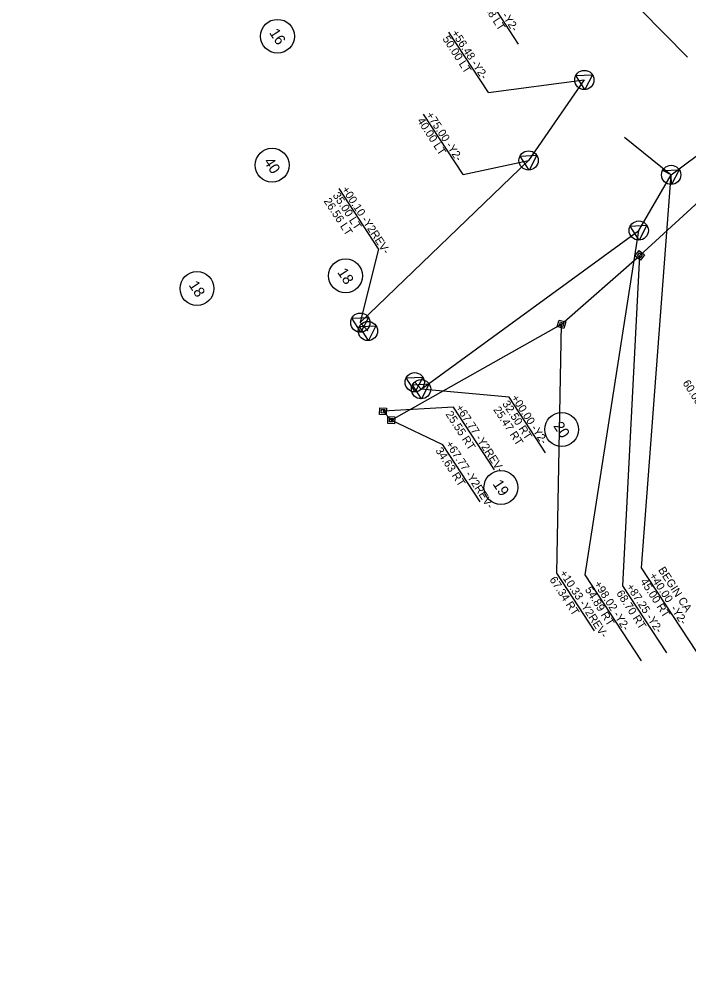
# Model space of a CAD drawing. Extents: x 1638966 to 1642158, y 841755 to 844938.
# Drawn here: x 1639805 to 1640306, y 843001 to 843723 of the extents above; entities that cross this region are included whole.
import ezdxf

# ---------------------------------------------------------------- set-up
doc = ezdxf.new("R2010")
doc.units = 0
for name, color, linetype in [('Exist Building', 7, 'Continuous'), ('Exist Guardrail Text', 7, 'Continuous'), ('Exist Other Culture Fence Line Text', 7, 'Continuous'), ('Exist Structure Major Deck Tunnel Box Culvert Text', 7, 'Continuous'), ('Exist Structure Minor Pipes CMP 18 Inch Text', 7, 'Continuous'), ('Exist Structure Minor Pipes CMP 24 Inch', 7, 'Continuous'), ('Exist Structure Minor Pipes RCP 24 Inch', 7, 'Continuous'), ('P_RDY_ROW_RW_CA_Lines', 7, 'Continuous'), ('Prop ROW Marker CA CELL', 7, 'Continuous'), ('Prop ROW Marker CELL', 7, 'Continuous')]:
    doc.layers.add(name, color=color, linetype=linetype)

msp = doc.modelspace()

# ---------------------------------------------------------------- linework, layer by layer
at = {"layer": 'Exist Building'}
for centre in [(1639998.43, 843710.36), (1639994.35, 843613.75), (1640049.39, 843530.85), (1639938.12, 843521.31), (1640211.14, 843415.72), (1640165.7, 843372.27)]:
    msp.add_circle(centre, 12.69, dxfattribs=at)
at = {"layer": 'Exist Guardrail Text'}
for p, q in [((1640156.32, 843668.13), (1640126.77, 843713.42)), ((1640137.31, 843606.79), (1640107.76, 843652.09)), ((1640271.05, 843312.1), (1640293.13, 843606.47)), ((1640074.1, 843550.98), (1640044.55, 843596.27)), ((1640228.83, 843306.86), (1640268.88, 843564.8)), ((1640171.81, 843439.81), (1640105.89, 843445.88)), ((1640199.01, 843398.12), (1640171.81, 843439.81)), ((1640312.04, 843249.28), (1640271.05, 843312.1)), ((1640270.86, 843242.45), (1640228.83, 843306.86))]:
    msp.add_line(p, q, dxfattribs=at)
for points in [[(1640156.32, 843668.13), (1640228.12, 843677.62)], [(1640137.31, 843606.79), (1640186.42, 843617.33)], [(1640074.1, 843550.98), (1640060.43, 843495.78)]]:
    msp.add_lwpolyline(points, dxfattribs=at)
at = {"layer": 'Exist Other Culture Fence Line Text'}
for points in [[(1640228.12, 843677.62), (1640186.42, 843617.33), (1640060.43, 843495.78), (1640066.12, 843489.53)], [(1640101.15, 843451.09), (1640105.89, 843445.88), (1640268.88, 843564.8), (1640293.13, 843606.47)], [(1640105.89, 843445.88), (1640101.15, 843451.09)]]:
    msp.add_lwpolyline(points, dxfattribs=at)
msp.add_arc((1640160.09, 843356.15), 355, 34.94361, 34.94361, dxfattribs=at)
at = {"layer": 'Exist Structure Major Deck Tunnel Box Culvert Text'}
msp.add_line((1640258.15, 843634.77), (1640293.13, 843606.47), dxfattribs=at)
msp.add_lwpolyline([(1640270.22, 843730.36), (1640305.26, 843694.61)], dxfattribs=at)
at = {"layer": 'Exist Structure Minor Pipes CMP 18 Inch Text'}
msp.add_line((1640178.92, 843704.51), (1640149.58, 843749.48), dxfattribs=at)
at = {"layer": 'Exist Structure Minor Pipes CMP 24 Inch'}
for p, q in [((1640257.02, 843298.67), (1640269.63, 843546.21)), ((1640207.51, 843308.13), (1640211.05, 843494.56)), ((1640130.11, 843432.48), (1640077.43, 843429.36)), ((1640160.76, 843385.52), (1640130.11, 843432.48)), ((1640122.25, 843404.14), (1640083.58, 843422.67)), ((1640150.11, 843361.45), (1640122.25, 843404.14)), ((1640235.8, 843264.77), (1640207.51, 843308.13)), ((1640289.91, 843248.26), (1640257.02, 843298.67))]:
    msp.add_line(p, q, dxfattribs=at)
at = {"layer": 'Exist Structure Minor Pipes RCP 24 Inch'}
for p, q in [((1640269.63, 843546.21), (1640348.28, 843618.3)), ((1640269.63, 843546.21), (1640269.63, 843546.21)), ((1640211.05, 843494.56), (1640211.05, 843494.56)), ((1640077.43, 843429.36), (1640077.43, 843429.36)), ((1640083.58, 843422.67), (1640083.58, 843422.67))]:
    msp.add_line(p, q, dxfattribs=at)
for points in [[(1640269.15, 843549.78), (1640273.2, 843546.69), (1640270.11, 843542.64), (1640266.06, 843545.73)], [(1640269.39, 843547.99), (1640271.42, 843546.45), (1640269.87, 843544.43), (1640267.85, 843545.97)], [(1640209.29, 843497.69), (1640214.19, 843496.32), (1640212.82, 843491.42), (1640207.92, 843492.79)], [(1640210.17, 843496.12), (1640212.62, 843495.44), (1640211.94, 843492.99), (1640209.49, 843493.67)], [(1640075, 843432.01), (1640080.08, 843431.79), (1640079.87, 843426.71), (1640074.78, 843426.92)], [(1640076.21, 843430.68), (1640078.76, 843430.57), (1640078.65, 843428.03), (1640076.11, 843428.14)], [(1640081.14, 843425.32), (1640086.23, 843425.1), (1640086.01, 843420.02), (1640080.92, 843420.23)], [(1640082.36, 843424), (1640084.9, 843423.89), (1640084.79, 843421.34), (1640082.25, 843421.45)]]:
    msp.add_lwpolyline(points, close=True, dxfattribs=at)
msp.add_lwpolyline([(1640077.43, 843429.36), (1640083.58, 843422.67), (1640211.05, 843494.56), (1640269.63, 843546.21)], dxfattribs=at)
at = {"layer": 'P_RDY_ROW_RW_CA_Lines'}
msp.add_line((1640293.13, 843606.47), (1640334.97, 843638.04), dxfattribs=at)
at = {"layer": 'Prop ROW Marker CELL'}
for p, q in [((1640228.12, 843677.62), (1640228.12, 843677.62)), ((1640186.42, 843617.33), (1640186.42, 843617.33)), ((1640286.79, 843609.9), (1640299.26, 843610.25)), ((1640293.13, 843606.47), (1640286.79, 843609.9)), ((1640293.35, 843599.26), (1640293.13, 843606.47)), ((1640299.26, 843610.25), (1640293.35, 843599.26)), ((1640268.88, 843564.8), (1640268.88, 843564.8)), ((1640060.43, 843495.78), (1640060.43, 843495.78)), ((1640066.12, 843489.53), (1640066.12, 843489.53)), ((1640101.15, 843451.09), (1640101.15, 843451.09)), ((1640105.89, 843445.88), (1640105.89, 843445.88))]:
    msp.add_line(p, q, dxfattribs=at)
for points in [[(1640221.69, 843680.89), (1640234.15, 843681.55), (1640228.52, 843670.42)], [(1640179.99, 843620.6), (1640192.45, 843621.26), (1640186.82, 843610.13)], [(1640262.45, 843568.06), (1640274.91, 843568.73), (1640269.28, 843557.59)], [(1640054, 843499.04), (1640066.46, 843499.71), (1640060.83, 843488.57)], [(1640059.69, 843492.8), (1640072.15, 843493.47), (1640066.52, 843482.33)], [(1640094.72, 843454.35), (1640107.18, 843455.02), (1640101.55, 843443.88)], [(1640099.46, 843449.15), (1640111.92, 843449.81), (1640106.29, 843438.68)]]:
    msp.add_lwpolyline(points, close=True, dxfattribs=at)
for centre in [(1640228.12, 843677.62), (1640186.42, 843617.33), (1640293.13, 843606.47), (1640268.88, 843564.8), (1640060.43, 843495.78), (1640066.12, 843489.53), (1640101.15, 843451.09), (1640105.89, 843445.88)]:
    msp.add_circle(centre, 7.2, dxfattribs=at)

# ---------------------------------------------------------------- texts
at = {"layer": 'Exist Building'}
for s, p in [('16', (1639991.92, 843713.02)), ('40', (1639987.85, 843616.41)), ('18', (1640042.88, 843533.51)), ('18', (1639931.61, 843523.97)), ('20', (1640204.63, 843418.38)), ('19', (1640159.19, 843374.93))]:
    msp.add_text(s, height=8, rotation=303.09057, dxfattribs=at).set_placement(p)
at = {"layer": 'Exist Guardrail Text'}
for s, p in [('+56.48 -Y2-', (1640128.39, 843712.76)), ('50.00 LT', (1640121.69, 843708.39)), ('40.00 LT', (1640102.68, 843647.06)), ('+75.00 -Y2-', (1640109.38, 843651.43)), ('35.00 LT', (1640039.47, 843591.24)), ('+00.10 -Y2REV-', (1640046.17, 843595.62)), ('26.56 LT', (1640032.77, 843586.87)), ('+00.00 -Y2-', (1640173.14, 843439.38)), ('25.47 RT', (1640159.74, 843430.64)), ('32.50 RT', (1640166.44, 843435.01)), ('BEGIN CA', (1640283.14, 843310.44)), ('45.00 RT', (1640269.74, 843301.7)), ('+40.00  -Y2-', (1640276.44, 843306.07))]:
    msp.add_text(s, height=6, rotation=303.12591, dxfattribs=at).set_placement(p)
at = {"layer": 'Exist Structure Minor Pipes CMP 18 Inch Text'}
for s, p in [('+85.00 -Y2-', (1640151.34, 843748.61)), ('129.38 LT', (1640144.64, 843744.23))]:
    msp.add_text(s, height=6, rotation=303.12591, dxfattribs=at).set_placement(p)
at = {"layer": 'Exist Structure Minor Pipes CMP 24 Inch'}
for s, p in [('+67.77 -Y2REV-', (1640131.54, 843432.07)), ('25.55 RT', (1640124, 843427.15)), ('34.63 RT', (1640116.43, 843399.94)), ('+67.77 -Y2REV-', (1640123.97, 843404.86)), ('+10.33 -Y2REV-', (1640209.31, 843308.11)), ('67.34 RT', (1640201.78, 843303.19)), ('68.70 RT', (1640251.82, 843292.97)), ('+87.25 -Y2-', (1640259.36, 843297.88))]:
    msp.add_text(s, height=6, rotation=303.12591, dxfattribs=at).set_placement(p)
at = {"layer": 'Prop ROW Marker CA CELL'}
for s, p in [('60.00 RT', (1640301.47, 843450.53)), ('+98.02 -Y2-', (1640235.09, 843299.97)), ('54.89 RT', (1640228.33, 843295.69))]:
    msp.add_text(s, height=6, rotation=302.31718, dxfattribs=at).set_placement(p)

doc.saveas('drawing.dxf')
